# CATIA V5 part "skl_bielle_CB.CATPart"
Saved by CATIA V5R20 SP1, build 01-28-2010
Part number: skl_bielle_CB
Publications: "Droite.4", "Droite.5", "Droite.6", "B", "C", "Plan.1"
Bounding box of the stored display mesh (mm): x -20.434 to 0, y 0 to 20, z 0 to 14.404
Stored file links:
  C:\Users\Matthieu\Desktop\IAO_2012_mcamard_Catia\skl_bielle_CB.CATPart
  C:\Users\Matthieu\Desktop\IAO_Artobolevsky\skl_Artoboloevsky_786.CATProduct
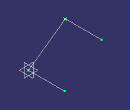
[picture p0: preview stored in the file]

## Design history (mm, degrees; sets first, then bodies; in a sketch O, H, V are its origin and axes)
Set1
  Line1: type Normal, RefPoint Point2, RefSkin Plane1, Start 0, End 20
  Line2: type PtDir, RefPoint Point1, Direction Plane1, Start 0, End 20
  Line3: type PtPt, FirstPoint Point1, SecondPoint Point2
Set2
  Point1 "B": linked copy from another document
  Point2 "C": linked copy from another document
  Plane1: linked copy from another document
Body1 (main body)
